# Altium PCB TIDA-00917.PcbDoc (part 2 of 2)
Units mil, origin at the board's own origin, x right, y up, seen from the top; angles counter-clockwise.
Board outline 4155.07 x 5505.31 mil, 2 copper layers (Top Layer, Bottom Layer), stack 62 mil thick; 134 components, 61 nets, 321 pads, 102 vias.
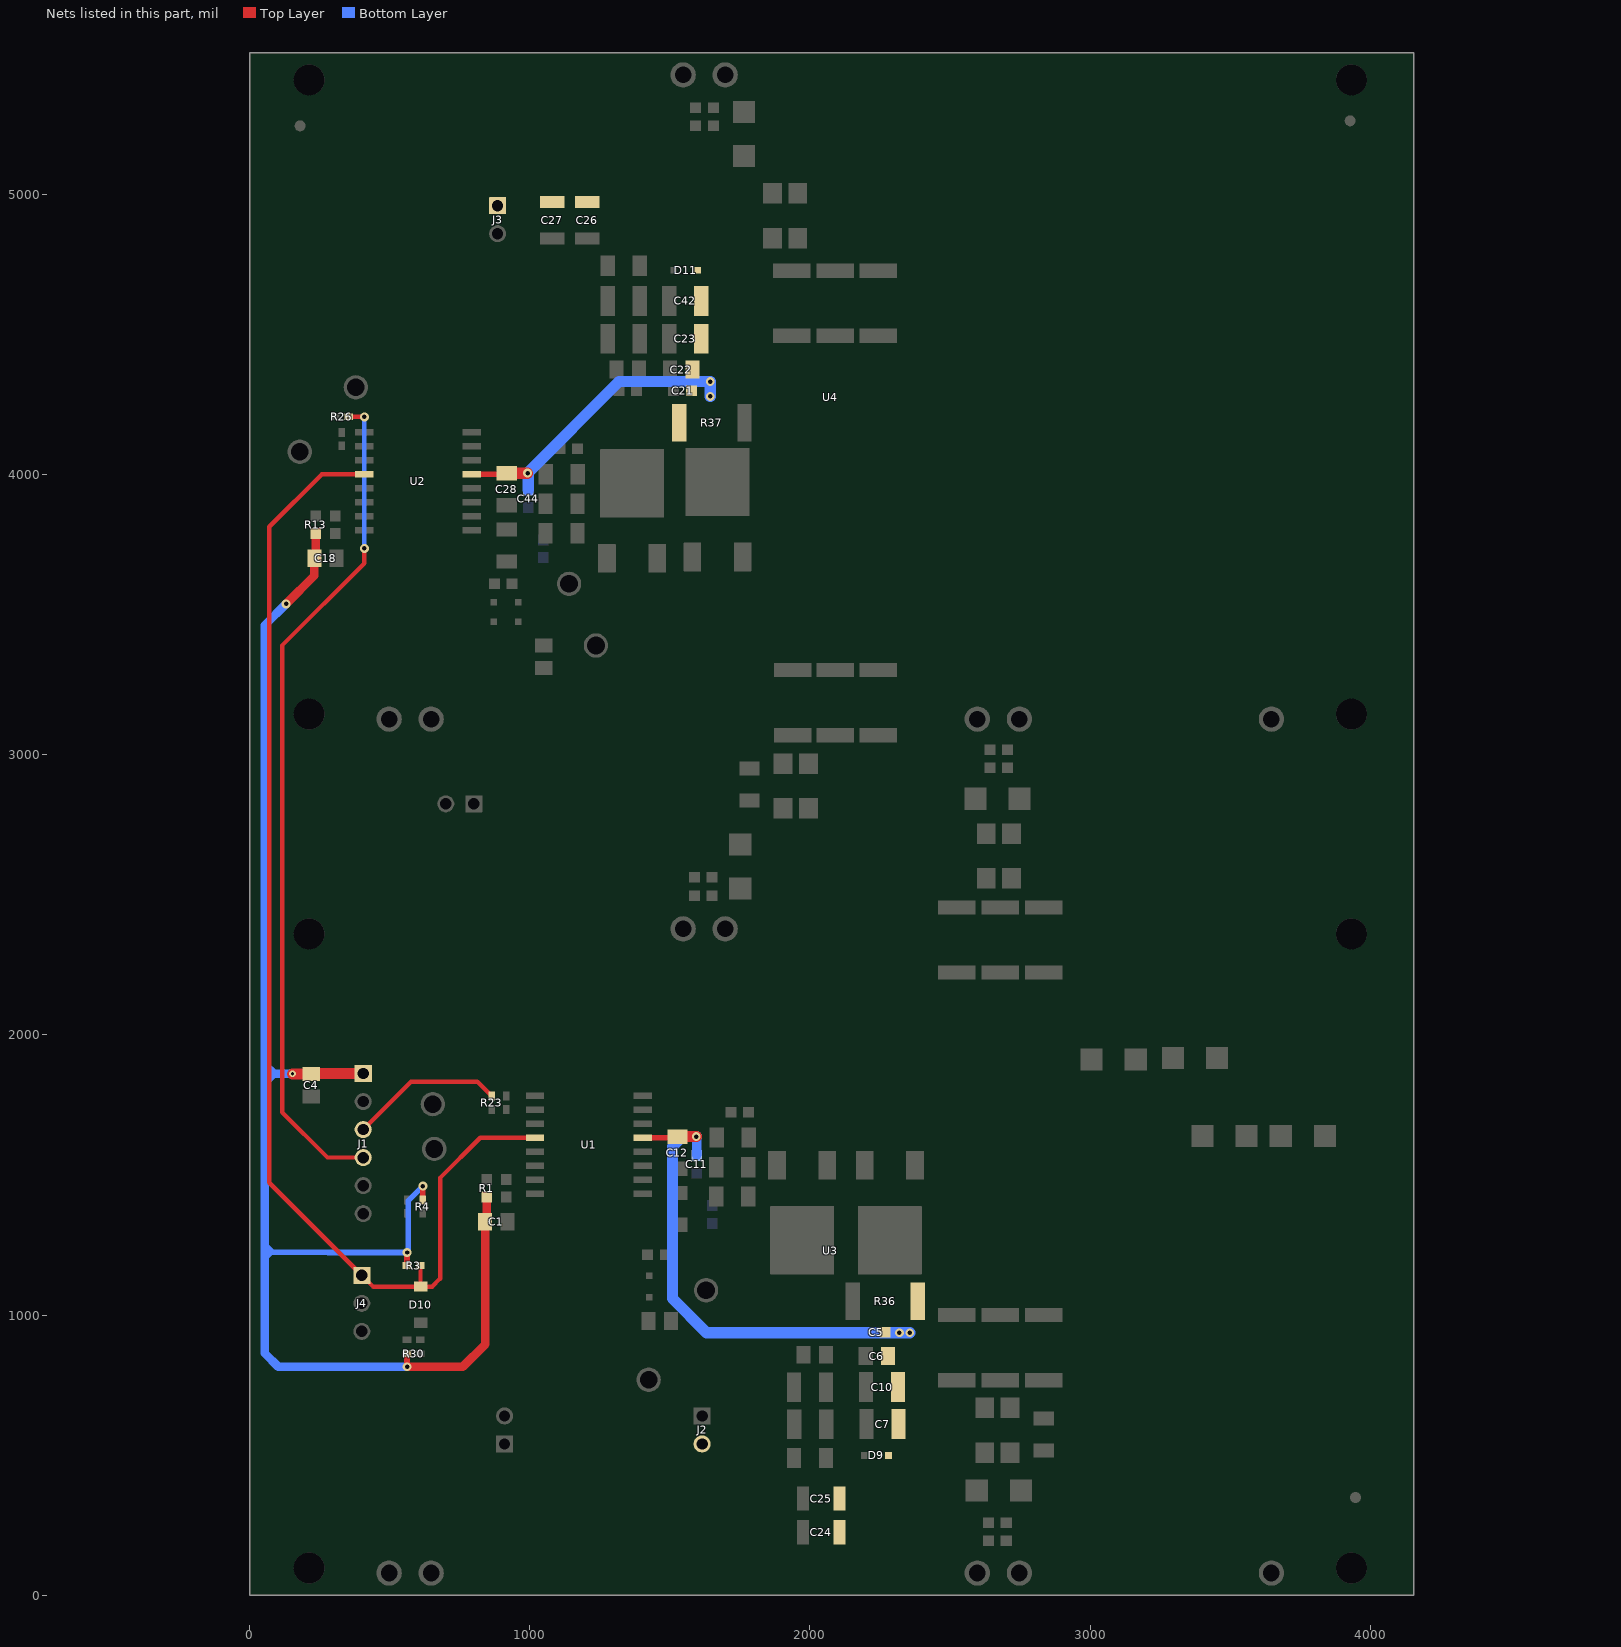
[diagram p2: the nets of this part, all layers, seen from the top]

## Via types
v1: diameter 32, hole 16, Top Layer to Bottom Layer, 97 vias
v2: diameter 24, hole 12, Top Layer to Bottom Layer, 5 vias

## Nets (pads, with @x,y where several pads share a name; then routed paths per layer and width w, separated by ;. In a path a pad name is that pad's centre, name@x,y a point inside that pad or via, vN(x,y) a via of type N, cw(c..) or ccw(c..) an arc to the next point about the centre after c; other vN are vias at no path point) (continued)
P5V: C1.1 C4.1 C18.1 J1.1 R1.1 R3.2 R4.2 R13.1 R30.2 | length 5792.7
  Top Layer w20: C18.1@230.77,3701.06 C18.1@235.77,3706.06 ; v1(561.62,815.67) R30.2@561.62,862.05 ; R3.2@561.62,1177.05 v1(561.62,1223.43) ; R4.2@618.43,1410.67 v1(618.43,1460.24) ; C1.1@840.77,1333 C1.1@845.77,1338
  Top Layer w30: v1(130.45,3539) 230.77,3639.32 C18.1@230.77,3701.06 ; C18.1@235.77,3706.06 R13.1@235.77,3789.56 ; v1(561.62,815.67) 760.67,815.67 840.77,895.77 C1.1@840.77,1333 ; C1.1@845.77,1338 R1.1@845.77,1421.5
  Top Layer w40: v2(153,1861) 219,1861 C4.1@220,1860 222.05,1862.05 J1.1@405.25,1862.05
  Bottom Layer w20: 54,1202 76.38,1224.38 ; 54,1224 54.38,1224.38 279.05,1224.38 280,1223.43 v1(561.62,1223.43) 566.62,1223.43 566.62,1408.43 v1(618.43,1460.24) ; 54,1252 54,1251.38 81,1224.38
  Bottom Layer w30: 54,1838 62,1838 86,1862 55,1893 54,1893 ; 54,1862 152,1862 v2(153,1861) ; v1(130.45,3539) 54,3462.55 54,1375.34 54,863.66 101.99,815.67 v1(561.62,815.67)
P15V_B: C21.2 C22.2 C23.2 C26.1 C27.1 C28.1 C42.2 C44.1 D11.1 J3.1 R37.2 U2.5 | length 1101.8
  Top Layer w20: U2.5@792.7,4001.06 912.95,4001.06 C28.1@917.04,4005.14
  Top Layer w40: C28.1@917.04,4005.14 917.18,4005 v1(992,4005)
  Bottom Layer w40: C44.1@994,3945.5 994,4003 v1(992,4005) 1319,4332 v1(1644,4332) v1(1644,4279)
P15V_T: C5.2 C6.2 C7.2 C10.2 C11.1 C12.1 C24.1 C25.1 D9.1 J2.2 R36.2 U1.5 | length 1772.3
  Top Layer w20: U1.5@1402.7,1633 1522.95,1633 C12.1@1527.04,1637.09 ; C12.1@1556.95,1633 C12.1@1561.04,1637.09
  Top Layer w40: C12.1@1561.04,1637.09 v1(1594.04,1637.09)
  Bottom Layer w30: v1(1594.04,1637.09) v1@1596.04,1635.09
  Bottom Layer w35: C11.1@1596.04,1570.5 v1@1596.04,1635.09
  Bottom Layer w40: v1(1594.04,1637.09) 1544.13,1637.09 1509.04,1602 1509.04,1059 1631.04,937 v1(2319.04,937) v1(2356.04,937)
PHASE: U3.10 U3.11 U4.10 U4.11
PWM_IN_B: J1.4 R26.1 | length 3016.5
  Top Layer w15: R26.1@352.66,4206.45 v1(409.04,4206.45) ; J1.4@405.25,1562.05 277.95,1562.05 116,1724 116,3390.41 409.04,3683.45 v1(409.04,3736.45)
  Bottom Layer w15: v1(409.04,3736.45) v1(409.04,4206.45)
PWM_IN_T: J1.3 R23.1 | length 550.8
  Top Layer w15: J1.3@405.25,1662.05 576.2,1833 812.58,1833 R23.1@863.96,1781.62
RDY: D10.1 J4.1 R3.1 U1.12 U2.12 | length 4368.9
  Top Layer w15: U2.12@408.84,4001.06 257.22,4001.06 70,3813.83 70,1472.29 J4.1@400.25,1142.05 440.78,1101.52 D10.1@610.25,1101.52 ; R3.1@610.25,1175.67 D10.1@610.25,1101.52 ; U1.12@1018.84,1633 823,1633 680,1490 680,1130 651.52,1101.52 D10.1@610.25,1101.52
  Top Layer w20: R3.1@610.25,1175.67 R3.1@608.87,1177.05 R3.1@610.25,1177.05
pads on no net: FID1.1 FID2.1 FID3.1 LBL1.0 U1.7 U2.7 U3.MH1 U3.MH2 U3.MH3 U3.MH4 U4.MH1 U4.MH2 U4.MH3 U4.MH4

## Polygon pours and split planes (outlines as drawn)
DGND on Bottom Layer "Top Layer-No Net" (solid, remove dead copper, pour order 130): 422,5034 443,5013 443,4958 443,3400.75 385,3350 385,2898.04 825.35,2457.69 1012.31,2457.69 1046,2424 1046,790.96 1009.04,754 121,754 25,850 25,5015 44,5034
EMITTER_T on Bottom Layer "Top Layer-No Net" (solid, remove dead copper, pour order 129): 2004.04,1169 1564.04,1169 1549.04,1184 1549.04,1439 1574.04,1464 2619.04,1464 2764.04,1609 2764.04,1697 2771.04,1704 2894.04,1704 2899.04,1699 2902.04,1696 2902.04,1692 2902.04,1527 2544.04,1169 2179.04,1169 2169.04,1159 2169.04,989.04 2155,975 2025,975 2019.04,980.96 2019.04,1154
GATE_T_ON on Bottom Layer "Top Layer-No Net" (solid, remove dead copper, pour order 122): 2190.54,1696.5 2190.54,1624 2200.54,1614 2736.04,1614 2743.04,1621 2743.04,1699 2738.04,1704 2505.54,1704 2198.04,1704
GATE_B_ON on Bottom Layer "Top Layer-No Net 1" (solid, pour order 165): 1700,3535 2000,3535 2184.76,3535 2313,3663.24 2313,3836 2313,3934 2307,3940 2179,3940 2175,3936 2175,3698 2117,3640 1800,3640 1701,3640 1695,3634 1695,3540
GATE_B_OFF on Bottom Layer "Top Layer-No Net 1" (solid, pour order 167): 1390,3535 1395,3530 1515,3530 1520,3535 1520,3655 1538,3673 2074,3673 2155,3754 2155,3934 2150,3939 2149,3940 2143,3940 2026,3940 2021,3935 2021,3834 1986,3799 1417,3799 1390,3772
EMITTER_B on Bottom Layer "Top Layer-No Net 1" (solid, pour order 175): 1994,3854 1233,3854 1133,3754 1121,3742 949,3742 930,3742 897,3775 896,3776 896,3900 900,3904 994,3904 1021,3904 1190,4073 1406,4073 1972,4073 2000,4045 2000,3860
EMITTER_B on Bottom Layer "Top Layer-No Net 1" (solid, pour order 177): 1375,4274 1479,4274 1495,4258 1495,4092 1538,4049 1323,4049 1360,4086 1360,4259
N8V_T on Top Layer "Top Layer-No Net" (solid, remove dead copper, pour order 132): 1429.04,1449 1374,1449 1370,1445 1370,1338.04 1416.04,1292 1646.04,1292 1679.04,1259 1679.04,1179 1718.04,1140 1831.04,1140 1841.04,1130 1894.04,1130 1894.04,1154 1894.04,1389 1852.12,1389 1812.12,1349 1469.04,1349 1439.04,1379 1439.04,1439
EMITTER_T on Top Layer "Top Layer-No Net" (solid, remove dead copper, pour order 131): 1614.04,1464 1614.04,1384 1604.04,1374 1512.35,1374 1489.04,1397.31 1489.04,1549 1494.04,1554 1569.04,1554 1574.04,1549 1574.04,1464.64 1574.68,1464
GATE_T_OFF on Top Layer "Top Layer-No Net" (solid, remove dead copper, pour order 128): 2589.04,1674 2588.65,1673.61 2588.65,1604 2459.04,1604 2444.04,1619 2359.04,1619 2344.43,1633.61 2344.43,1733.61 2329.04,1749 2104.04,1749 1944.04,1589 1944.04,1484 1939.04,1479 1854.04,1479 1844.04,1489 1844.04,1645.04 2033,1834 2409.04,1834 2419.04,1824 2419.04,1709 2419.04,1704 2424.04,1699 2439.04,1699 2449.04,1699 2459.04,1709 2583.65,1709 2588.65,1704
NetL4_4 on Top Layer "Top Layer-No Net" (solid, remove dead copper, pour order 110): 2024.04,4706.45 2024.04,4781.45 2018.04,4787.45 1928.04,4787.45 1924.04,4791.45 1919.04,4796.45 1919.04,4836.45 1919.04,4891.45 1924.04,4896.45 2309.04,4896.45 2324.04,4881.45 2324.04,4696.45 2314.04,4686.45 2029.04,4686.45 2024.04,4691.45
NetL4_1 on Top Layer "Top Layer-No Net" (solid, remove dead copper, pour order 108): 2004.04,4763.02 2004.04,4693.26 1997.03,4686.25 1824.24,4686.25 1814.04,4696.45 1814.04,4886.18 1824.31,4896.45 1894.04,4896.45 1899.04,4891.45 1899.04,4806.45 1899.04,4771.45 1904.04,4766.45 2000.61,4766.45 2004.04,4763.02
NetL2_3 on Top Layer "Top Layer-No Net" (solid, remove dead copper, pour order 98): 2025.04,3110 2025.04,3025 2019.04,3019 1964.04,3019 1959.04,3014 1959.04,2984 1959.04,2924 1964.04,2919 2314.04,2919 2319.04,2924 2320.81,2925.77 2320.81,3089 2320.81,3102.23 2314.04,3109 2303.84,3119.2 2034.24,3119.2
NetL2_2 on Top Layer "Top Layer-No Net" (solid, remove dead copper, pour order 97): 1737.78,2919 1934.04,2919 1939.04,2924 1939.04,3039 1944.04,3044 2004.04,3044 2004.04,3112.19 2002.03,3114.2 1997.03,3119.2 1914.04,3119.2 1744.24,3119.2 1734.04,3109 1734.04,2922.74
GATE_B_ON on Top Layer "Top Layer-No Net" (solid, remove dead copper, pour order 105): 2189.04,4604 2299.04,4604 2313.04,4590 2313.04,3278 2299.04,3264 2185.85,3264 2175.04,3274.81 2175.04,4590
GATE_B_OFF on Top Layer "Top Layer-No Net" (solid, remove dead copper, pour order 106): 2035.04,4604 2145.04,4604 2159.04,4590 2159.04,3278 2145.04,3264 2031.85,3264 2021.04,3274.81 2021.04,4590
EMITTER_T on Top Layer "Top Layer-No Net" (solid, remove dead copper, pour order 99): 2771.04,2264.35 2896.04,2264.35 2902.04,2258.35 2902.04,963.81 2897.23,959 2770.85,959 2764.04,965.81 2764.04,2257.35
GATE_T_ON on Top Layer "Top Layer-No Net" (solid, remove dead copper, pour order 101): 2616.2,2264.35 2739.04,2264.35 2747.04,2256.35 2747.04,963.81 2742.23,959 2615.85,959 2609.04,965.81 2609.04,2257.19
NetL1_1 on Top Layer "Top Layer-No Net" (solid, remove dead copper, pour order 88): 2769.04,799 2769.04,719 2764.04,714 2684.04,714 2679.04,709 2679.04,614 2684.04,609 2689.04,604 2854.04,604 2899.04,604 2904.04,604 2909.04,609 2910.81,610.77 2910.81,802.23 2904.04,809 2779.04,809
GATE_T_OFF on Top Layer "Top Layer-No Net" (solid, remove dead copper, pour order 102): 2460.2,2263.35 2587.88,2263.35 2592.04,2259.19 2592.04,963.81 2587.23,959 2460.85,959 2454.04,965.81 2454.04,2257.19
GATE_T_ON on Top Layer "Top Layer-No Net" (solid, remove dead copper, pour order 115): 2164.04,1699 2164.04,1489 2169.04,1484 2234.04,1484 2239.04,1489 2239.04,1609 2244.04,1614 2314.04,1614 2324.04,1624 2324.04,1704 2314.04,1714 2174.04,1714 2164.04,1704
EMITTER_B on Top Layer "Top Layer-No Net" (solid, remove dead copper, pour order 107): 1879.04,4604 1989.04,4604 2003.04,4590 2003.04,3278 1989.04,3264 1875.85,3264 1865.04,3274.81 1865.04,4590
NetC34_1 on Top Layer "Top Layer-No Net" (solid, remove dead copper, pour order 124): 2659.04,287.54 2659.04,49 2659.04,44 2644.04,29 2539.04,29 2529.04,39 2529.04,549 2534.04,554 2654.04,554 2659.04,549 2659.04,419
NetC34_2 on Top Layer "Top Layer-No Net" (solid, remove dead copper, pour order 125): 2679.04,544 2679.04,449 2679.04,44 2694.04,29 2704.04,29 2884.04,29 2899.04,44 2899.04,549 2894.04,554 2684.04,554 2679.04,549
NetL1_4 on Top Layer "Top Layer-No Net" (solid, remove dead copper, pour order 127): 2659.04,714 2659.04,614 2649.04,604 2464.04,604 2454.04,614 2454.04,802.19 2461.05,809.2 2738.84,809.2 2749.04,799 2749.04,744 2744.04,739 2665.61,739 2659.04,732.43
NetC37_1 on Top Layer "Top Layer-No Net" (solid, remove dead copper, pour order 89): 2664.04,3034 2664.04,2674 2654.04,2664 2534.04,2664 2524.04,2674 2524.04,3174 2539.04,3189 2649.04,3189 2664.04,3174
NetL3_2 on Top Layer "Top Layer-No Net" (solid, remove dead copper, pour order 123): 2684.04,2600 2684.04,2519 2687.04,2516 2757.04,2516 2763.04,2510 2769.04,2504 2769.04,2419 2774.24,2413.8 2902.61,2413.8 2910.81,2422 2910.81,2593.23 2902.04,2602 2896.04,2608 2687.04,2608 2684.04,2605
NetL3_3 on Top Layer "Top Layer-No Net" (solid, remove dead copper, pour order 121): 2664.04,2598 2664.04,2489 2668.04,2485 2744.04,2485 2748.04,2481 2748.04,2419.81 2742.03,2413.8 2454.24,2413.8 2447.04,2421 2447.04,2601 2454.04,2608 2660.04,2608 2664.04,2604
NetC37_2 on Top Layer "Top Layer-No Net" (solid, remove dead copper, pour order 90): 2684.04,3034 2684.04,3169 2699.04,3184 2704.04,3189 2714.04,3189 2799.04,3189 2814.04,3174 2814.04,2809 2814.04,2674 2804.04,2664 2694.04,2664 2684.04,2674
NetQ1_4 on Top Layer "Top Layer-No Net 1" (solid, pour order 135): 2125,985 2125,1130 2160,1165 2160,1380 2170,1390 2405,1390 2410,1385 2410,1155 2400,1145 2285,1145 2225,1085 2225,992.01 2217.05,984.06 2125.94,984.06
P15V_T on Top Layer "Top Layer-No Net 1" (solid, pour order 137): 2250,885 2250,425 2235,410 2225.12,400.12 2090,400.12 2075.12,400.12 2060,385 2060,160 2045,145 1680,145 1665,160 1665,560 1655,570 1650,575 1595,575 1560,575 1540,555 1540,480 1540,55 1560,35 2405,35 2415,45 2415,875 2415,1010 2415,1115 2410,1120 2334.06,1120 2325,1110.94 2325,1042.54 2250,967.54
N8V_T on Top Layer "Top Layer-No Net 1" (solid, pour order 139): 1840.04,1376.92 1840.04,280.04 1835,275 1805,275 1800,280 1800,495 1800,695 1795,700 1550,700 1540,690 1540,610 1550,600 1690,600 1700,590 1700,575 1700,190 1715,175 1990,175 2000,185 2003.04,188.04 2003.04,274.14 2003.04,1132 2011.04,1140 2093.04,1140 2101.17,1148.13 2101.17,1376.87 2089.04,1389 1851.12,1389 1842.12,1380
EMITTER_T on Top Layer "Top Layer-No Net 1" (solid, pour order 141): 2230,945 2230,470 2215,455 2040,455 2030,465 2020,475 2020,1055 2020,1065 2030,1075 2095,1075 2100,1070 2105,1065 2105,980 2105,965 2110,960 2215,960
EMITTER_B on Top Layer "Top Layer-No Net" (solid, remove dead copper, pour order 143): 1004.04,3832.06 1004.04,3752.05 994.04,3742.06 902.35,3742.06 879.04,3765.37 879.04,3917.06 884.04,3922.05 959.04,3922.06 964.04,3917.06 964.04,3832.69 964.68,3832.06
N8V_B on Top Layer "Top Layer-No Net 1" (solid, pour order 145): 861,4891 1306,4891 1320,4877 1320,4690 1320,4425 1335,4410 1335,4120 1360,4095 1475,4095 1485,4085 1485,3850 1475,3840 1250,3840 1240,3850 1240,4135 1230,4145 1140,4145 1130,4135 1130,4068.51 1125,4063.51 1086.49,4063.51 1075,4075 1075,4735 1060,4750 860,4750 840,4770 840,4870
P15V_B on Top Layer "Top Layer-No Net 1" (solid, pour order 147): 1451,4911 1560,4802 1560,4400 1560,4260 1550.94,4250.94 1505.94,4250.94 1500,4245 1500,4125 1505.94,4119.05 1653.06,4119.06 1676,4142 1676,4892 1523,5045 850,5045 840,5035 840,4932.11 861.11,4911
EMITTER_B on Top Layer "Top Layer-No Net 1" (solid, pour order 149): 1367,4134 1360,4141 1360,4685 1350,4695 1350,4780 1360,4790 1520,4790 1530,4780 1530,4280 1526,4276 1496,4276 1495,4276 1479,4263 1479,4140 1473,4134
NetQ3_4 on Top Layer "Top Layer-No Net 1" (solid, pour order 151): 1724.8,4242.99 1724.8,4109.8 1713,4098 1547,4098 1540,4091 1540,3860 1550,3850 1789.92,3850 1799.92,3860 1799.92,4250.08 1790,4260 1730,4260 1725,4255
NetC38_1 on Top Layer "Top Layer-No Net 1" (solid, pour order 153): 1635,5338.54 1635,5220 1640,5215 1895,5215 1920,5190 1920,5045 1920,4965 1925,4960 1987,4960 1995,4968 1995,5287 1932,5350 1760,5350 1750,5360 1750,5465 1735,5480 1650,5480 1635,5465
NetC38_2 on Top Layer "Top Layer-No Net 1" (solid, pour order 155): 1900,5000 1900,5170 1890,5180 1625,5180 1615,5190 1615,5460 1595,5480 1495,5480 1490,5475 1490,5110 1505,5095 1750,5095 1765,5095 1785,5075 1785,4970 1795,4960 1895,4960 1900,4965
NetC36_2 on Top Layer "Top Layer-No Net 1" (solid, pour order 157): 1610,2515 1610,2345 1595,2330 1505,2330 1495,2340 1495,2710 1500,2715 1530,2745 1725,2745 1730,2745 1740,2755 1740,2866.39 1748.61,2875 1930,2875 1940,2865 1940,2775 1900,2735 1890,2725 1796.5,2631.5 1621.5,2631.5 1610,2620
NetC36_1 on Top Layer "Top Layer-No Net 1" (solid, pour order 159): 1630,2495 1630,2585 1635,2590 1806,2590 1960,2744 1960,2786.64 1960,2865 1970,2875 2050,2875 2060,2865 2060,2692 1825.28,2457.28 1757.28,2457.28 1750,2450 1750,2340 1740,2330 1645,2330 1630,2345
GATE_B_ON on Top Layer "Top Layer-No Net 1" (solid, pour order 161): 1695,3600 1695,3770 1705.94,3780.94 1819.06,3780.94 1825,3775 1825,3570 1825,3540 1820,3535 1700,3535 1695,3540
GATE_B_OFF on Top Layer "Top Layer-No Net 1" (solid, pour order 163): 1390,3595 1390,3750 1395,3755 1510,3755 1520,3745 1520,3565 1520,3535 1515,3530 1395,3530 1390,3535

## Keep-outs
Keep-Out Layer:
  pour cut-out: 444,3366.11 1053,2760.72 1053,-4 1368,-4 1368,2907.04 758,3517.04 758,5505.32 444,5505.32
  text ".Layer_Name" at -465.96,-984.49 h60

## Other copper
Top Layer:
  text ".Layer_Name" at -465.96,-984.49 h60
Bottom Layer:
  text ".Layer_Name" at -465.96,-984.49 h60

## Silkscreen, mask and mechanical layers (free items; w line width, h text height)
Top Overlay:
  lines w6: 1616,4305 1680,4305 1686,4305 1703,4322
  text "+15V_B" at 577,4941 h30
  text "-8V_B" at 602,4838 h30
  text ".PRJ_Number" at 3017,4411 h100
  text "REV - E1" at 3064,4236 h100
  text "THERMISTOR CONTACT" at 519,2649 h30
  text "+5V" at 541,1852 h30
  text "GND" at 187,1705 h30
  text "PWM_IN_T" at 45,1643 h30
  text "PWM_IN_B" at 45,1559 h30
  text "GND" at 182,1448 h30
  text "FAULT" at 123,1347 h30
  text "READY" at 118,1122 h30
  text "GND" at 179,1029 h30
  text "RESET" at 125,929 h30
  text "-8V_T" at 1336,628 h30
  text "+15V_T" at 1311,523 h30
  text "THERMISTOR CONTACT" at 629,424 h30
  text ".Layer_Name" at -465.96,-984.49 h60
Bottom Overlay:
  circle w10: c1970,2452.04 r5
  circle w10: c1696,5487 r7.07
  lines w7.87: 0,0 0.07,0.07 ; 0.07,0.07 0,2457.35 4155,2457.35 4155,0.07 0.07,0.07 ; -0.07,5505.89 0,3048.62 4154.93,3048.62 4154.93,5505.89 -0.07,5505.89
  text ".Layer_Name" at -465.96,-984.49 h60
Top Paste:
  text ".Layer_Name" at -465.96,-984.49 h60
Bottom Paste:
  text ".Layer_Name" at -465.96,-984.49 h60
Top Solder:
  text ".Layer_Name" at -465.96,-984.49 h60
  text ".Layer_Name" at -465.96,-984.49 h60
Bottom Solder:
  text ".Layer_Name" at -465.96,-984.49 h60
M1 Board Outline:
  the board outline again, w10
M2 Board Dimensions:
  rectangle: -1042.96,-401 -917.96,-276
  rectangle: -917.96,-526 -542.96,-401
  lines w7: -1042.96,-401 -42.96,-401 ; -917.96,-526 -917.96,-276 ; -792.96,-526 -792.96,-276 ; -542.96,-526 -542.96,-276 ; -292.96,-526 -292.96,-276 ; -1042.96,-526 -42.96,-526 -42.96,-276 -1042.96,-276 -1042.96,-526
M3 3D STEP Top:
  text ".Layer_Name" at -465.96,-984.49 h60
M4 3D STEP Bottom:
  text ".Layer_Name" at -465.96,-984.49 h60
M5 Assembly Top:
  circle w6: c1615,640 r18.36
  circle w6: c2373,1431 r18.36
  circle w6: c2062,1431 r18.36
  circle w6: c885,4960 r18.36
  circle w6: c800,2825 r18.36
  circle w6: c910,540 r18.36
  circle w6: c400.25,1142.05 r18.36
  circle w6: c405.25,1862.05 r18.36
  circle w10: c1276,3802 r18.25
  circle w10: c1581,3813 r21.09
  lines w10: -1334.96,-1056.17 5265.04,-1056.17 ; -1334.96,-852.83 5267.04,-852.83 ; -1334.96,-649.5 -1334.96,-1259.5 2670.04,-1259.5 5267.04,-1259.5 5267.04,-649.5 -1334.46,-649.5 -1334.46,-1259.5 241.04,-1259.5 ; 1130.04,-1259.5 1130.04,-649.5 ; 2397.04,-852.83 2397.04,-649.5 ; 3237.04,-852.83 3237.04,-649.5 ; 3859.04,-1266 3859.04,-1063.17
  text "COMPONENTS MARKED 'DNP' SHOULD NOT BE POPULATED." at 110.54,-444.5 h30
  text "ASSEMBLY VARIANT:" at 110.04,-560 h30
  text ".VariantName" at 1146.04,-560 h30
  text "PCB VIEWED FROM TOP SIDE" at -1271.46,-781.67 h30
  text "BOARD #:" at 1205.04,-781.67 h30
  text ".PRJ_Number" at 1750.54,-781.67 h30
  text "REV:" at 2595.04,-781.67 h30
  text ".PCB_Rev" at 2886.54,-781.67 h30
  text "SVN REV:" at 3433.04,-781.67 h30
  text ".VersionControl_RevNumber" at 3939.04,-781.67 h30
  text "TID #:" at 1205.04,-985 h30
  text ".TID" at 1750.54,-985 h30
  text "PLOT NAME =" at -1271.46,-1190.34 h30
  text ".plot_File_Name" at -465.96,-1190.34 h30
  text "GENERATED    :" at 1207.04,-1190.34 h30
  text ".Print_Date" at 2076.54,-1190.34 h30
  text ".Print_Time" at 2805.54,-1190.34 h30
  text "TEXAS INSTRUMENTS" at 4070.04,-1190.34 h30
M6 Assembly Bottom:
  circle w10: c1970,2390 r30.41
  circle w10: c1697.24,5426.57 r46.46
  lines w7.87: -0.07,2457.28 4154.93,2457.28 4154.93,0 0,0 -0.07,2457.28 ; 0,5505.96 0.07,3048.69 4155,3048.69 4155,5505.96 0,5505.96
  lines w10: -1335.46,-853.33 5266.54,-853.33 ; -1333.46,-1056.67 5266.54,-1056.67 ; 72.54,-1266.5 72.54,-1063.67 ; 694.54,-853.33 694.54,-650 ; 1534.54,-853.33 1534.54,-650 ; 2801.54,-1260 2801.54,-650 ; 3690.54,-1260 5266.04,-1260 5266.04,-650 -1335.46,-650 -1335.46,-1260 1261.54,-1260 5266.54,-1260 5266.54,-650
  text "COMPONENTS MARKED 'DNP' SHOULD NOT BE POPULATED." at 5059.04,-444 h30
  text ".VariantName" at 4015.04,-560 h30
  text "ASSEMBLY VARIANT:" at 5054.04,-560 h30
  text ".VersionControl_RevNumber" at -7.46,-782.17 h30
  text "SVN REV:" at 498.54,-782.17 h30
  text ".PCB_Rev" at 1045.04,-782.17 h30
  text "REV:" at 1336.54,-782.17 h30
  text ".PRJ_Number" at 2181.04,-782.17 h30
  text "BOARD #:" at 2726.54,-782.17 h30
  text "PCB VIEWED FROM BOTTOM SIDE" at 5203.04,-782.17 h30
  text ".TID" at 2181.04,-985.5 h30
  text "TID #:" at 2726.54,-985.5 h30
  text "TEXAS INSTRUMENTS" at -138.46,-1190.84 h30
  text ".Print_Time" at 1126.04,-1190.84 h30
  text ".Print_Date" at 1855.04,-1190.84 h30
  text "GENERATED    :" at 2724.54,-1190.84 h30
  text ".plot_File_Name" at 4397.54,-1190.84 h30
  text "PLOT NAME =" at 5203.04,-1190.84 h30
M9 Title Sheet:
  drawing of 57 lines, arcs and shapes, not listed
  text "1" at -303.12,7910.5 h70
  text "2" at 2192.54,7910.5 h70
  text "3" at 4681.88,7910.5 h70
  text "4" at 7188.55,7910.5 h70
  text "5" at 9687.54,7910.5 h70
  text "6" at 12192.54,7910.5 h70
  text "A" at -1459.46,6767.5 h70
  text "A" at 13340.54,6767.5 h70
  text "B" at -1459.46,4387.5 h70
  text "B" at 13340.54,4387.5 h70
  text "C" at -1459.46,2012.5 h70
  text "C" at 13340.54,2012.5 h70
  text "PROJECT TITLE:" at 10300.54,151.5 h45
  text ".PRJ_Title" at 10350.54,18.17 h70
  text "DESIGNED FOR:" at 10300.54,-149.5 h45
  text ".PRJ_Customer" at 10350.54,-289.5 h70
  text "D" at -1459.46,-357.5 h70
  text "D" at 13340.54,-357.5 h70
  text "FILE NAME:" at 10300.54,-449.5 h45
  text ".PCB_File_Name_No_Path" at 10350.54,-569.5 h70
  text "Texas Instruments (TI) and/or its licensors do not warrant the accuracy or completeness of this specification" at 5331.04,-731.34 h45
  text "ENGINEER:" at 10300.54,-739.5 h45
  text "LAYOUT BY:" at 11805.54,-739.5 h45
  text "or any information contained therein. TI and/or its licensors do not warrant that this design will meet" at 5286.05,-844 h45
  text ".PRJ_Engineer" at 10350.54,-894.49 h70
  text ".PCB_Layout" at 11856.04,-894.49 h70
  text "the specifications, will be suitable for your application or fit for any particular purpose, or will operate in" at 5286.05,-956.67 h45
  text "ALTIUM DESIGNER VERSION:" at 11805.54,-1049.5 h45
  text "an implementation. TI and/or its licensors do not warrant that the design is production worthy. You should" at 5286.05,-1069.33 h45
  text "completely validate and test your design implementation to confirm the system functionality for your application." at 5331.04,-1182 h45
  text ".print_Scale" at 10350.54,-1182.83 h70
  text ".Application_BuildNumber" at 11856.04,-1182.83 h70
  text "1" at -303.12,-1389.5 h70
  text "2" at 2192.54,-1389.5 h70
  text "3" at 4681.88,-1389.5 h70
  text "4" at 7188.55,-1389.5 h70
  text "5" at 9687.54,-1389.5 h70
  text "6" at 12192.54,-1389.5 h70
M10 Fab Notes:
  drawing of 227 lines, arcs and shapes, not listed
  text "DESIGN INFORMATION" at 11326.5,6674.72 h60
  text "(REFER ALSO ARRAY/PANEL PROFILING INFORMATION)" at 10974.98,6508.64 h60
  text "BOARD SIZE" at 10288.98,6504.36 h60
  text "139.84MM" at 11412,6386 h60
  text "105.54MM" at 10665,6384 h60
  text "X" at 11256.98,6376.54 h60
  text "Number of Layers :" at 10691.98,6179.36 h60
  text "2" at 11764.52,6174.36 h60
  text "15" at 11765.45,6042.56 h60
  text "MIN. TRACK WIDTH:" at 10691.98,6040.36 h60
  text "MIL" at 11942.98,6040.36 h60
  text "8" at 11786,5909 h60
  text "MIN. CLEARANCE:" at 10691.98,5908.36 h60
  text "MIL" at 11942.98,5908.36 h60
  text "12" at 11755.45,5787.56 h60
  text "MIN. VIA DRILL SIZE:" at 10691.98,5776.36 h60
  text "MIL" at 11942.98,5776.36 h60
  text "6 MIL ( 0.1524 mm)" at 11386.98,5634.65 h60
  text "MINIMUM ANNULAR RING" at 10362.75,5630.36 h60
  text "EXTERNAL" at 12278.52,5619.36 h60
  text "PER" at 10562.75,5512.36 h60
  text "IPC-D-275 CLASS 2 LEVEL C" at 10782.75,5512.36 h60
  text "MIL, HOLES" at 12270.98,5400.07 h60
  text "+/-" at 11878.52,5399.36 h60
  text "+/-" at 12732.52,5399.36 h60
  text "REGISTRATION TOLERANCES:" at 10362.75,5394.36 h60
  text "METAL" at 11562.52,5394.36 h60
  text "5" at 12138.72,5394.36 h60
  text "3" at 12971.72,5394.36 h60
  text "MIL" at 13087.98,5394.36 h60
  text "MATERIAL:" at 10287.98,5184.9 h60
  text "FR-4 High Tg" at 11274.42,5044.57 h60
  text "FR-408" at 10708.98,5036 h60
  text "X" at 11115.52,5036.36 h60
  text "OTHER" at 12196.98,5036 h60
  text "63 MIL (1.6mm) +/-10%" at 11029.08,4873.28 h60
  text "THICKNESS:" at 10362.75,4869 h60
  text "X" at 10900.92,4869 h60
  text "OTHER" at 12313.98,4869 h60
  text "TOLERANCE:" at 10362.75,4711 h60
  text "X" at 11202.05,4711 h60
  text "ANSI IPC-6012 TYPE 3 CLASS 2" at 11388.99,4711 h60
  text "OTHER +/-" at 11388.98,4555 h60
  text "BOW & TWIST:" at 10362.75,4398 h60
  text "X" at 11202.05,4398 h60
  text "ANSI IPC-6012 TYPE 3 CLASS 2" at 11388.99,4398 h60
  text "OTHER +/-" at 11388.98,4239.49 h60
  text "COPPER THICKNESS (FINISHED):" at 10287.98,4104 h60
  text "1.4MIL (1oz)" at 11167.98,3951.28 h60
  text "2MIL (1.4oz)" at 11934.98,3951.28 h60
  text "2.8MIL (2oz)" at 12661.98,3951.28 h60
  text "OUTER:" at 10644.98,3947 h60
  text "X" at 11039.52,3946.36 h60
  text "N/A" at 12661.52,3794.64 h60
  text "1.4MIL (1oz)" at 11167.98,3794.28 h60
  text "2.8MIL (2oz)" at 11934.98,3794.28 h60
  text "INNER SIGNAL:" at 10355.9,3790 h60
  text "X" at 12532,3783 h60
  text "DRILLING:" at 10287.98,3651 h60
  text "REFERENCE:" at 10362.75,3534 h60
  text "X" at 11010.98,3534 h60
  text "AS SHOWN" at 11197.98,3534 h60
  text "X" at 11911.98,3534 h60
  text "NC_DRILL FILES" at 12048.98,3534 h60
  text "PTH MIN COPPER THICKNESS:" at 10362.75,3376 h60
  text "X" at 11712.98,3376 h60
  text "1MIL" at 11849.98,3376 h60
  text "OTHER" at 12346.98,3376 h60
  text "BOARD FINISH:" at 10287.98,3217 h60
  text "SILKSCREEN:" at 10443.2,3099 h60
  text "X" at 11391.98,3099 h60
  text "TOP" at 11517.98,3099 h60
  text "X" at 11901.98,3099 h60
  text "BOTTOM" at 12028.98,3099 h60
  text "SILKSCREEN COLOR:" at 10443.2,2932 h60
  text "X" at 11390.94,2932 h60
  text "WHITE" at 11517.98,2932 h60
  text "OTHER" at 12028.98,2932 h60
  text "SOLDER RESIST COLOR:" at 10443.2,2762 h60
  text "X" at 11010.94,2602.8 h60
  text "GREEN" at 11137.98,2602.8 h60
  text "BLUE" at 11728.98,2602.8 h60
  text "OTHER" at 12266.98,2602.8 h60
  text "IMMERSION GOLD (ENIG)" at 11348.98,2414.28 h60
  text "ENEPIG" at 12686.52,2411 h60
  text "SURFACE FINISH:" at 10287.98,2410 h60
  text "X" at 11162.03,2410 h60
  text "IMM. TIN/SILVER OR EQUIV" at 10617.52,2253 h60
  text "OTHER" at 12048.98,2253 h60
  text "ARRAY/PANEL:" at 10287.98,2074 h60
  text "CUT AND TRIM PER MECH LAYER 1" at 11348.98,2069.71 h60
  text "N.C. ROUTE" at 11348.98,1918 h60
  text "X" at 12027.98,1918 h60
  text "V. SCORE" at 12214.98,1918 h60
  text "CERTIFICATION:" at 10287.98,1781 h60
  text "MATERIALS AND WORKMANSHIP FOR ALL PCBS" at 11012.98,1781 h60
  text "TO MEET OR EXCEED THE REQUIREMENTS OF:" at 11012.98,1683 h60
  text "X" at 10639.48,1546.49 h60
  text "ANSI IPC-A-600F CLASS ->" at 10778.48,1546.49 h60
  text "X" at 12417.54,1546.49 h60
  text "2" at 12536.48,1546.49 h60
  text "1" at 12221.48,1545 h60
  text "3" at 12890.48,1545 h60
  text "X" at 10641.54,1387 h60
  text "UL 94V-0" at 10778.48,1387 h60
  text "X" at 11453.54,1387 h60
  text "RoHS" at 11590.48,1387 h60
  text "OTHER" at 12234.88,1387 h60
  text "PER ORDER" at 12631.94,1387 h60
  text "X" at 12574,1257 h60
  text "VIA TENTING:" at 11505.52,1253.36 h60
  text "ADDITIONAL REQUIREMENTS:" at 10287.98,1246 h60
  text "YES" at 12055.19,1244.28 h60
  text "NO" at 12419.99,1239.05 h60
  text "MICROSECTION:" at 10362.75,1131 h60
  text "YES" at 11268.48,1131 h60
  text "IMPEDANCE CONTROL:" at 11527.52,1124.36 h60
  text "YES" at 12511.52,1123.36 h60
  text "X" at 13053.52,1116.36 h60
  text "NO" at 12886.99,1106.05 h60
  text "REQUIRED" at 12129.98,974.85 h60
  text "BARE BOARD ELEC. TEST:" at 10362.75,972 h60
  text "NONE" at 11668.48,972 h60
  text "X" at 12002.98,972 h60
  text "PER ORDER" at 12721.98,972 h60
  text "MANUFACTURER'S UL:" at 10362.75,815 h60
  text "RAIL" at 11528.48,810.71 h60
  text "METAL" at 12020.29,810.71 h60
  text "SILK" at 12531.98,810.71 h60
  text "X" at 12395.52,810.36 h60
M11 Gerber Information:
  lines w10: -1334.96,-1056.17 5265.04,-1056.17 ; -1334.96,-852.83 5267.04,-852.83 ; -1334.96,-649.5 -1334.96,-1259.5 2670.04,-1259.5 5267.04,-1259.5 5267.04,-649.5 -1334.46,-649.5 -1334.46,-1259.5 241.04,-1259.5 ; 1130.04,-1259.5 1130.04,-649.5 ; 2397.04,-852.83 2397.04,-649.5 ; 3237.04,-852.83 3237.04,-649.5 ; 3859.04,-1266 3859.04,-1063.17
  text "ALL ARTWORK VIEWED FROM TOP SIDE" at -1271.46,-781.67 h60
  text "BOARD #:" at 1205.04,-781.67 h60
  text ".PRJ_Number" at 1750.54,-781.67 h60
  text "REV:" at 2595.04,-781.67 h60
  text ".PCB_Rev" at 2886.54,-781.67 h60
  text "SVN REV:" at 3433.04,-781.67 h60
  text ".VersionControl_RevNumber" at 3939.04,-781.67 h60
  text "LAYER NAME =" at -1271.46,-984.49 h60
  text "TID #:" at 1205.04,-985 h60
  text ".TID" at 1750.54,-985 h60
  text "PLOT NAME =" at -1271.46,-1190.34 h60
  text ".plot_File_Name" at -465.96,-1190.34 h60
  text "GENERATED    :" at 1207.04,-1190.34 h60
  text ".Print_Date" at 2076.54,-1190.34 h60
  text ".Print_Time" at 2805.54,-1190.34 h60
  text "TEXAS INSTRUMENTS" at 4070.04,-1190.34 h60
M12 Stackup:
  lines w6: 10503.5,7462.72 13053.5,7462.72 ; 10503.5,7567.12 13053.5,7567.12 ; 10443.5,6977.72 ccw(c10477.5,6977.72) 10477.5,6943.72 13079.5,6943.72 ccw(c13079.5,6977.72) 13113.5,6977.72 13113.5,7683.72 ccw(c13079.5,7683.72) 13079.5,7717.72 10477.5,7717.72 ccw(c10477.5,7683.72) 10443.5,7683.72 10443.5,6977.72
  text "Layer Stack Up Detail for: TIDA-00917-E1.Pcbdoc" at 10503.5,7599.82 h57
  text "Layer" at 10503.5,7528.12 h24
  text "Gerber" at 11399.31,7528.12 h24
  text "Copper" at 11962.83,7528.12 h24
  text "Dielectric" at 12565.54,7528.12 h24
  text "Name" at 10503.5,7480.12 h24
  text "Document" at 11399.31,7480.12 h24
  text "Thickness" at 11962.83,7480.12 h24
  text "Material" at 12565.54,7480.12 h24
  text "Top Solder Mask" at 10518.5,7388.72 h34
  text "(.GTS)" at 11399.31,7387.16 h34
  text "Solder Resist" at 12565.54,7387.16 h34
  text "Top Layer" at 10513.5,7293.72 h34
  text "(.GTL)" at 11399.31,7290.41 h34
  text "1.4mil" at 11962.83,7290.41 h34
  text "FR4-High Tg" at 12594.5,7289.72 h34
  text "FR4-High Tg" at 12599.5,7206.72 h34
  text "Bottom Layer" at 10508.5,7205.72 h34
  text "(.GBL)" at 11407.5,7201.72 h34
  text "1.4mil" at 11967.5,7195.72 h34
  text "Solder Resist" at 12559.5,7128.72 h34
  text "(.GBS)" at 11404.5,7121.72 h34
  text "Bottom Solder Mask" at 10513.5,7120.72 h34
M13 Component Bodies Top:
  text ".Layer_Name" at -465.96,-984.49 h60
M14 Component Bodies Bottom:
  text ".Layer_Name" at -465.96,-984.49 h60
M15 Courtyards Top:
  text ".Layer_Name" at -465.96,-984.49 h60
M16 Courtyards Bottom:
  text ".Layer_Name" at -465.96,-984.49 h60
Drill Drawing:
  text ".legend" at 6274,1023 h60
  text "Drill Table" at 6284,873 h60
  text "FOR 12MIL DRILL +0/-12MIL" at 6284,753 h60
  text "FOR 16MIL DRILL +0/-16MIL" at 6284,648 h60
  text "FOR PTH DRILL +/-3MIL" at 6279.73,561.45 h60
  text "FOR NPTH DRILL +/-2MIL" at 6284,478 h60
  text ".Layer_Name" at -465.96,-984.49 h60
M17 Embedded Cavity:
  text ".Layer_Name" at -465.96,-984.49 h60
M18 Embedded Assembly:
  text ".Layer_Name" at -465.96,-984.49 h60
M19 Embedded Keepout:
  text ".Layer_Name" at -465.96,-984.49 h60

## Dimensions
0,0 to 0,5505.31 on M2 Board Dimensions
0,0 to 4155.07,0 on M2 Board Dimensions
-1042.96,-526 to -42.96,-526 on M2 Board Dimensions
